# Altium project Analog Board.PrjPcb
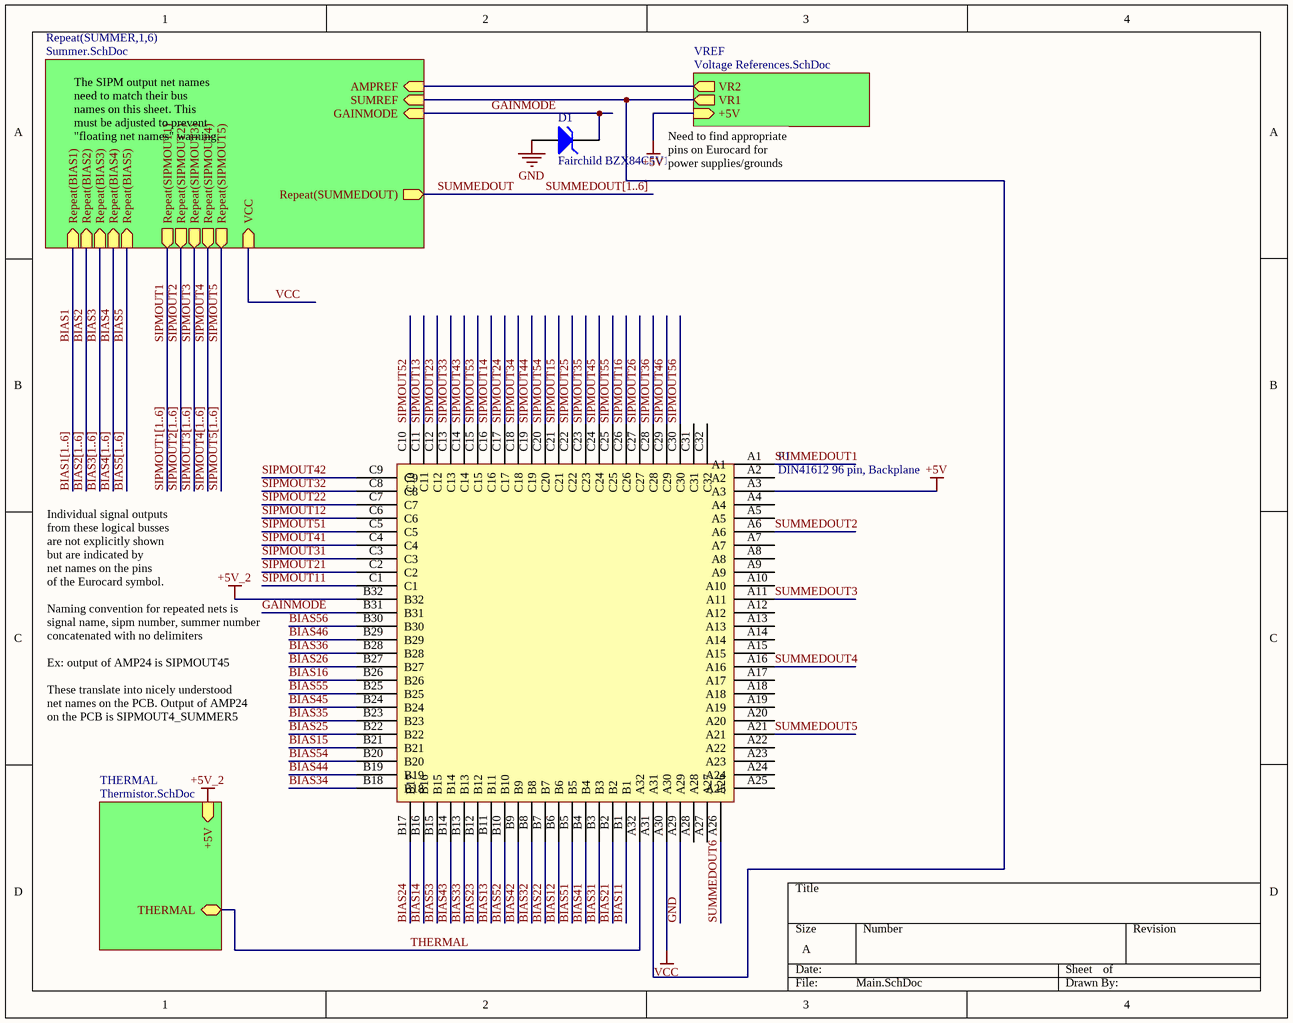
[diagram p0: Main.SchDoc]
5 sheets, 884 parts. Net scope: hierarchical (ports join the sheet entries above them; power ports are global).
Board files: Test PCB.PcbDoc, Amplifier Board.PcbDoc
Sheets:
  Main.SchDoc
    SUMMER1 = Summer.SchDoc
      AMP1 = Amplifier.SchDoc
      AMP2 = Amplifier.SchDoc
      AMP3 = Amplifier.SchDoc
      AMP4 = Amplifier.SchDoc
      AMP5 = Amplifier.SchDoc
    SUMMER2 = Summer.SchDoc
      AMP1 = Amplifier.SchDoc
      AMP2 = Amplifier.SchDoc
      AMP3 = Amplifier.SchDoc
      AMP4 = Amplifier.SchDoc
      AMP5 = Amplifier.SchDoc
    SUMMER3 = Summer.SchDoc
      AMP1 = Amplifier.SchDoc
      AMP2 = Amplifier.SchDoc
      AMP3 = Amplifier.SchDoc
      AMP4 = Amplifier.SchDoc
      AMP5 = Amplifier.SchDoc
    SUMMER4 = Summer.SchDoc
      AMP1 = Amplifier.SchDoc
      AMP2 = Amplifier.SchDoc
      AMP3 = Amplifier.SchDoc
      AMP4 = Amplifier.SchDoc
      AMP5 = Amplifier.SchDoc
    SUMMER5 = Summer.SchDoc
      AMP1 = Amplifier.SchDoc
      AMP2 = Amplifier.SchDoc
      AMP3 = Amplifier.SchDoc
      AMP4 = Amplifier.SchDoc
      AMP5 = Amplifier.SchDoc
    SUMMER6 = Summer.SchDoc
      AMP1 = Amplifier.SchDoc
      AMP2 = Amplifier.SchDoc
      AMP3 = Amplifier.SchDoc
      AMP4 = Amplifier.SchDoc
      AMP5 = Amplifier.SchDoc
    VREF = Voltage References.SchDoc
    THERMAL = Thermistor.SchDoc

## Sheet Main.SchDoc
size A

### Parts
D1  Fairchild BZX84C5V1  [SOT23]
P1  DIN41612 96 pin, Backplane  [EURO2.54-2H96]

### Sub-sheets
Repeat(SUMMER,1,6) = Summer.SchDoc: Repeat(BIAS1) (in), Repeat(SUMMEDOUT) (out), Repeat(SIPMOUT2) (out), Repeat(SIPMOUT5) (out), Repeat(SIPMOUT1) (out), Repeat(SIPMOUT3) (out), Repeat(SIPMOUT4) (out), Repeat(BIAS2) (in), Repeat(BIAS3) (in), Repeat(BIAS4) (in), Repeat(BIAS5) (in), AMPREF (in), SUMREF (in), GAINMODE (in), VCC (in)
THERMAL = Thermistor.SchDoc: THERMAL, +5V (in)
VREF = Voltage References.SchDoc: VR2 (out), VR1 (out), +5V (in)

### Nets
+5V: P1.A3 ; sheet VREF/+5V
+5V_2: P1.B32 ; sheet THERMAL/+5V
GND: D1.1(A) P1.A29
VCC: P1.A30 ; sheet Repeat(SUMMER,1,6)/VCC
BASE1: P1.A31 ; sheet Repeat(SUMMER,1,6)/SUMREF, sheet VREF/VR1
BASE2: sheet Repeat(SUMMER,1,6)/AMPREF, sheet VREF/VR2
BIAS11: P1.B1  [project net BIAS1]
BIAS12: P1.B6  [project net BIAS1]
BIAS13: P1.B11  [project net BIAS1]
BIAS14: P1.B16  [project net BIAS1]
BIAS15: P1.B21  [project net BIAS1]
BIAS16: P1.B26  [project net BIAS1]
BIAS21: P1.B2  [project net BIAS2]
BIAS22: P1.B7  [project net BIAS2]
BIAS23: P1.B12  [project net BIAS2]
BIAS24: P1.B17  [project net BIAS2]
BIAS25: P1.B22  [project net BIAS2]
BIAS26: P1.B27  [project net BIAS2]
BIAS31: P1.B3  [project net BIAS3]
BIAS32: P1.B8  [project net BIAS3]
BIAS33: P1.B13  [project net BIAS3]
BIAS34: P1.B18  [project net BIAS3]
BIAS35: P1.B23  [project net BIAS3]
BIAS36: P1.B28  [project net BIAS3]
BIAS41: P1.B4  [project net BIAS4]
BIAS42: P1.B9  [project net BIAS4]
BIAS43: P1.B14  [project net BIAS4]
BIAS44: P1.B19  [project net BIAS4]
BIAS45: P1.B24  [project net BIAS4]
BIAS46: P1.B29  [project net BIAS4]
BIAS51: P1.B5  [project net BIAS5]
BIAS52: P1.B10  [project net BIAS5]
BIAS53: P1.B15  [project net BIAS5]
BIAS54: P1.B20  [project net BIAS5]
BIAS55: P1.B25  [project net BIAS5]
BIAS56: P1.B30  [project net BIAS5]
GAINMODE: D1.2(K) P1.B31 ; sheet Repeat(SUMMER,1,6)/GAINMODE
SIPMOUT11: P1.C1  [project net SIPMOUT1]
SIPMOUT12: P1.C6  [project net SIPMOUT1]
SIPMOUT13: P1.C11  [project net SIPMOUT1]
SIPMOUT14: P1.C16  [project net SIPMOUT1]
SIPMOUT15: P1.C21  [project net SIPMOUT1]
SIPMOUT16: P1.C26  [project net SIPMOUT1]
SIPMOUT21: P1.C2  [project net SIPMOUT2]
SIPMOUT22: P1.C7  [project net SIPMOUT2]
SIPMOUT23: P1.C12  [project net SIPMOUT2]
SIPMOUT24: P1.C17  [project net SIPMOUT2]
SIPMOUT25: P1.C22  [project net SIPMOUT2]
SIPMOUT26: P1.C27  [project net SIPMOUT2]
SIPMOUT31: P1.C3  [project net SIPMOUT3]
SIPMOUT32: P1.C8  [project net SIPMOUT3]
SIPMOUT33: P1.C13  [project net SIPMOUT3]
SIPMOUT34: P1.C18  [project net SIPMOUT3]
SIPMOUT35: P1.C23  [project net SIPMOUT3]
SIPMOUT36: P1.C28  [project net SIPMOUT3]
SIPMOUT41: P1.C4  [project net SIPMOUT4]
SIPMOUT42: P1.C9  [project net SIPMOUT4]
SIPMOUT43: P1.C14  [project net SIPMOUT4]
SIPMOUT44: P1.C19  [project net SIPMOUT4]
SIPMOUT45: P1.C24  [project net SIPMOUT4]
SIPMOUT46: P1.C29  [project net SIPMOUT4]
SIPMOUT51: P1.C5  [project net SIPMOUT5]
SIPMOUT52: P1.C10  [project net SIPMOUT5]
SIPMOUT53: P1.C15  [project net SIPMOUT5]
SIPMOUT54: P1.C20  [project net SIPMOUT5]
SIPMOUT55: P1.C25  [project net SIPMOUT5]
SIPMOUT56: P1.C30  [project net SIPMOUT5]
SUMMEDOUT1: P1.A1  [project net SUMMEDOUT]
SUMMEDOUT2: P1.A6  [project net SUMMEDOUT]
SUMMEDOUT3: P1.A11  [project net SUMMEDOUT]
SUMMEDOUT4: P1.A16  [project net SUMMEDOUT]
SUMMEDOUT5: P1.A21  [project net SUMMEDOUT]
SUMMEDOUT6: P1.A26  [project net SUMMEDOUT]
THERMAL: P1.A32 ; sheet THERMAL/THERMAL

Not connected (* = marked no-connect by the designer): P1 A2 A4 A5 A7 A8 A9 A10 A12 A13 A14 A15 A17 A18 A19 A20 A22 A23 A24 A25 A27 A28 C31 C32

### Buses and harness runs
bus BIAS1[1..6]
bus BIAS2[1..6]
bus BIAS3[1..6]
bus BIAS4[1..6]
bus BIAS5[1..6]
bus SIPMOUT1[1..6]
bus SIPMOUT2[1..6]
bus SIPMOUT3[1..6]
bus SIPMOUT4[1..6]
bus SIPMOUT5[1..6]
bus SUMMEDOUT[1..6]

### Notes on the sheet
- The SIPM output net names need to match their bus names on this sheet. This must be adjusted to prevent "floating net names" warning.
- Need to find appropriate pins on Eurocard for power supplies/grounds
- Individual signal outputs
  from these logical busses
  are not explicitly shown
  but are indicated by
  net names on the pins
  of the Eurocard symbol.
  Naming convention for repeated nets is
  signal name, sipm number, summer number
  concatenated with no delimiters
  Ex: output of AMP24 is SIPMOUT45
  These translate into nicely understood
  net names on the PCB. Output of AMP24
  on the PCB is SIPMOUT4_SUMMER5

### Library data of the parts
D1 = D Zener: Zener Diode

## Sheet Summer.SchDoc
size A
Used 6 times, as channels SUMMER1, SUMMER2, SUMMER3, SUMMER4, SUMMER5, SUMMER6. Parts and nets are listed once, with the designators drawn on the sheet.
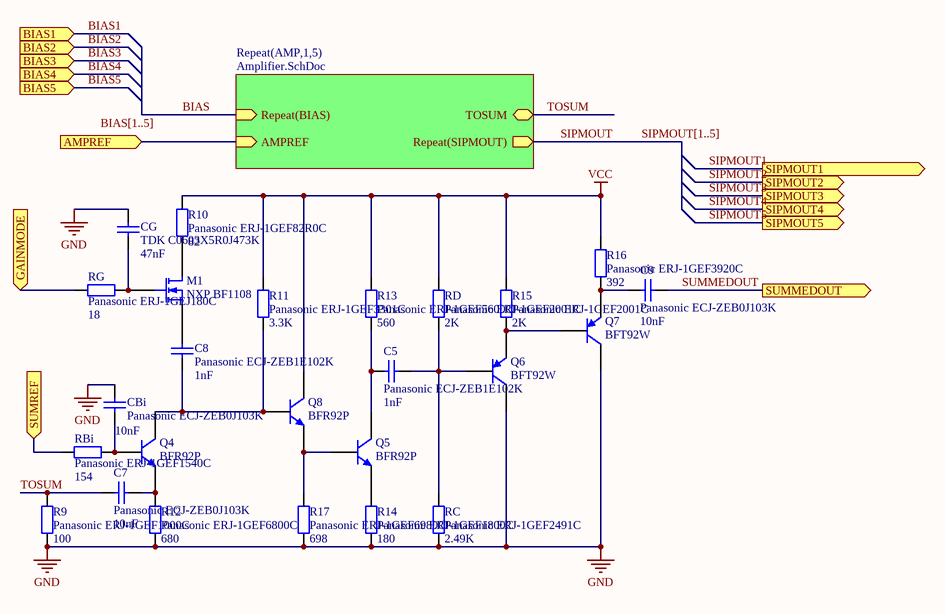
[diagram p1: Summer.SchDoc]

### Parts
C5  Panasonic ECJ-ZEB1E102K  value 1nF  [RESC0603L]
C7  Panasonic ECJ-ZEB0J103K  value 10nF  [RESC0603L]
C8  Panasonic ECJ-ZEB1E102K  value 1nF  [RESC0603L]
C9  Panasonic ECJ-ZEB0J103K  value 10nF  [RESC0603L]
CBi  Panasonic ECJ-ZEB0J103K  value 10nF  [RESC0603L]
CG  TDK C0603X5R0J473K  value 47nF  [RESC0603L]
M1  NXP BF1108  [SOT-143]
Q4  BFR92P  [SOT23_N]
Q5  BFR92P  [SOT23_N]
Q6  BFT92W  [SOT323_L]
Q7  BFT92W  [SOT323_L]
Q8  BFR92P  [SOT23_N]
R9  Panasonic ERJ-1GEF1000C  value 100  [RESC0603L]
R10  Panasonic ERJ-1GEF82R0C  value 82  [RESC0603L]
R11  Panasonic ERJ-1GEF3301C  value 3.3K  [RESC0603L]
R12  Panasonic ERJ-1GEF6800C  value 680  [RESC0603L]
R13  Panasonic ERJ-1GEF5600C  value 560  [RESC0603L]
R14  Panasonic ERJ-1GEF1800C  value 180  [RESC0603L]
R15  Panasonic ERJ-1GEF2001C  value 2K  [RESC0603L]
R16  Panasonic ERJ-1GEF3920C  value 392  [RESC0603L]
R17  Panasonic ERJ-1GEF6980C  value 698  [RESC0603L]
RBi  Panasonic ERJ-1GEF1540C  value 154  [RESC0603L]
RC  Panasonic ERJ-1GEF2491C  value 2.49K  [RESC0603L]
RD  Panasonic ERJ-1GEF2001C  value 2K  [RESC0603L]
RG  Panasonic ERJ-1GEJ180C  value 18  [RESC0603L]

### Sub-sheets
Repeat(AMP,1,5) = Amplifier.SchDoc: Repeat(BIAS) (in), TOSUM (bidir), Repeat(SIPMOUT) (out), AMPREF (in)

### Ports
AMPREF (in), BIAS1 (in), BIAS2 (in), BIAS3 (in), BIAS4 (in), BIAS5 (in), GAINMODE (in), SIPMOUT1 (out), SIPMOUT2 (out), SIPMOUT3 (out), SIPMOUT4 (out), SIPMOUT5 (out), SUMMEDOUT (out), SUMREF (in)

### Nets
GND: CBi.2 CG.2 Q6.3(C) Q7.3(C) R9.1 R12.1 R14.1 R17.1 RC.1
VCC: Q8.3(C) R10.2 R11.2 R13.2 R15.2 R16.2 RD.2
AMPREF: port AMPREF, sheet Repeat(AMP,1,5)/AMPREF
GAINMODE: RG.2 ; port GAINMODE
SUMMEDOUT: C9.2 ; port SUMMEDOUT
SUMREF: RBi.1 ; port SUMREF
TOSUM: C7.1 R9.2 ; sheet Repeat(AMP,1,5)/TOSUM
NetC5_1: C5.1 Q5.3(C) R13.1
NetC5_2: C5.2 Q6.1(B) RC.2 RD.1
NetC7_2: C7.2 Q4.2(E) R12.2
NetC8_1: C8.1 Q4.3(C) Q8.1(B) R11.1
NetC8_2: C8.2 M1.3(S)
NetC9_1: C9.1 Q7.2(E) R16.1
NetCBi_1: CBi.1 Q4.1(B) RBi.2
NetCG_1: CG.1 M1.1(G) RG.1
NetM1_4: M1.4(D) R10.1
NetQ5_1: Q5.1(B) Q8.2(E) R17.2
NetQ5_2: Q5.2(E) R14.2
NetQ6_2: Q6.2(E) Q7.1(B) R15.1

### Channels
SUMMER1: designators end in _SUMMER1; ports AMPREF=BASE2 BIAS1=BIAS1 BIAS2=BIAS2 BIAS3=BIAS3 BIAS4=BIAS4 BIAS5=BIAS5 GAINMODE=GAINMODE SIPMOUT1=SIPMOUT1 SIPMOUT2=SIPMOUT2 SIPMOUT3=SIPMOUT3 SIPMOUT4=SIPMOUT4 SIPMOUT5=SIPMOUT5 SUMMEDOUT=SUMMEDOUT SUMREF=BASE1
SUMMER2: designators end in _SUMMER2; ports AMPREF=BASE2 BIAS1=BIAS1 BIAS2=BIAS2 BIAS3=BIAS3 BIAS4=BIAS4 BIAS5=BIAS5 GAINMODE=GAINMODE SIPMOUT1=SIPMOUT1 SIPMOUT2=SIPMOUT2 SIPMOUT3=SIPMOUT3 SIPMOUT4=SIPMOUT4 SIPMOUT5=SIPMOUT5 SUMMEDOUT=SUMMEDOUT SUMREF=BASE1
SUMMER3: designators end in _SUMMER3; ports AMPREF=BASE2 BIAS1=BIAS1 BIAS2=BIAS2 BIAS3=BIAS3 BIAS4=BIAS4 BIAS5=BIAS5 GAINMODE=GAINMODE SIPMOUT1=SIPMOUT1 SIPMOUT2=SIPMOUT2 SIPMOUT3=SIPMOUT3 SIPMOUT4=SIPMOUT4 SIPMOUT5=SIPMOUT5 SUMMEDOUT=SUMMEDOUT SUMREF=BASE1
SUMMER4: designators end in _SUMMER4; ports AMPREF=BASE2 BIAS1=BIAS1 BIAS2=BIAS2 BIAS3=BIAS3 BIAS4=BIAS4 BIAS5=BIAS5 GAINMODE=GAINMODE SIPMOUT1=SIPMOUT1 SIPMOUT2=SIPMOUT2 SIPMOUT3=SIPMOUT3 SIPMOUT4=SIPMOUT4 SIPMOUT5=SIPMOUT5 SUMMEDOUT=SUMMEDOUT SUMREF=BASE1
SUMMER5: designators end in _SUMMER5; ports AMPREF=BASE2 BIAS1=BIAS1 BIAS2=BIAS2 BIAS3=BIAS3 BIAS4=BIAS4 BIAS5=BIAS5 GAINMODE=GAINMODE SIPMOUT1=SIPMOUT1 SIPMOUT2=SIPMOUT2 SIPMOUT3=SIPMOUT3 SIPMOUT4=SIPMOUT4 SIPMOUT5=SIPMOUT5 SUMMEDOUT=SUMMEDOUT SUMREF=BASE1
SUMMER6: designators end in _SUMMER6; ports AMPREF=BASE2 BIAS1=BIAS1 BIAS2=BIAS2 BIAS3=BIAS3 BIAS4=BIAS4 BIAS5=BIAS5 GAINMODE=GAINMODE SIPMOUT1=SIPMOUT1 SIPMOUT2=SIPMOUT2 SIPMOUT3=SIPMOUT3 SIPMOUT4=SIPMOUT4 SIPMOUT5=SIPMOUT5 SUMMEDOUT=SUMMEDOUT SUMREF=BASE1

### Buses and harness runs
bus BIAS[1..5]
bus SIPMOUT[1..5]

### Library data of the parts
C5 C7-C9 CBi CG = Cap: Capacitor
M1 = MOSFET-N: N-Channel MOSFET; PackageDocument: 1995/1996
Q4 Q5 Q8 = BFR92A: NPN 5 GHz Wideband Transistor
Q6 Q7 = BFT92W: PNP 4 GHz Wideband Transistor
R9-R17 RBi RC RD RG = Res2: Resistor

## Sheet Amplifier.SchDoc
size A
Used 30 times, as channels SUMMER1/AMP1, SUMMER1/AMP2, SUMMER1/AMP3, SUMMER1/AMP4, SUMMER1/AMP5, SUMMER2/AMP1, SUMMER2/AMP2, SUMMER2/AMP3, SUMMER2/AMP4, SUMMER2/AMP5, SUMMER3/AMP1, SUMMER3/AMP2, SUMMER3/AMP3, SUMMER3/AMP4, SUMMER3/AMP5, SUMMER4/AMP1, SUMMER4/AMP2, SUMMER4/AMP3, SUMMER4/AMP4, SUMMER4/AMP5, SUMMER5/AMP1, SUMMER5/AMP2, SUMMER5/AMP3, SUMMER5/AMP4, SUMMER5/AMP5, SUMMER6/AMP1, SUMMER6/AMP2, SUMMER6/AMP3, SUMMER6/AMP4, SUMMER6/AMP5. Parts and nets are listed once, with the designators drawn on the sheet.
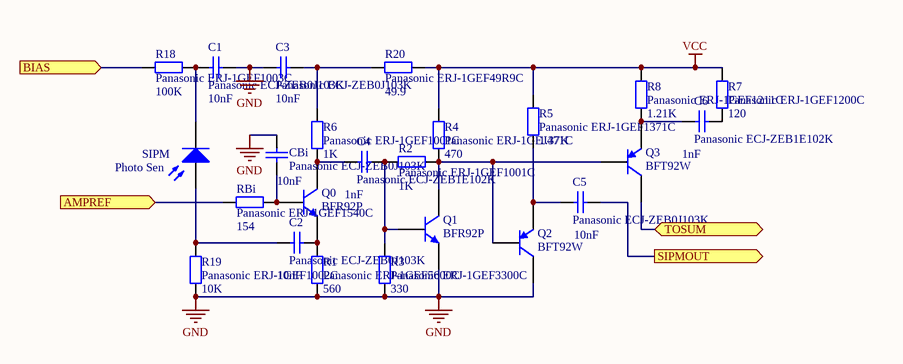
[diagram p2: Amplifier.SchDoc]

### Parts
C1  Panasonic ECJ-ZEB0J103K  value 10nF  [RESC0603L]
C2  Panasonic ECJ-ZEB0J103K  value 10nF  [RESC0603L]
C3  Panasonic ECJ-ZEB0J103K  value 10nF  [RESC0603L]
C4  Panasonic ECJ-ZEB1E102K  value 1nF  [RESC0603L]
C5  Panasonic ECJ-ZEB0J103K  value 10nF  [RESC0603L]
C6  Panasonic ECJ-ZEB1E102K  value 1nF  [RESC0603L]
CBi  Panasonic ECJ-ZEB0J103K  value 10nF  [RESC0603L]
Q0  BFR92P  [SOT23_N]
Q1  BFR92P  [SOT23_N]
Q2  BFT92W  [SOT323_L]
Q3  BFT92W  [SOT323_L]
R1  Panasonic ERJ-1GEF5600C  value 560  [RESC0603L]
R2  Panasonic ERJ-1GEF1001C  value 1K  [RESC0603L]
R3  Panasonic ERJ-1GEF3300C  value 330  [RESC0603L]
R4  Panasonic ERJ-1GEJ471C  value 470  [RESC0603L]
R5  Panasonic ERJ-1GEF1371C  value 1.37K  [RESC0603L]
R6  Panasonic ERJ-1GEF1001C  value 1K  [RESC0603L]
R7  Panasonic ERJ-1GEF1200C  value 120  [RESC0603L]
R8  Panasonic ERJ-1GEF1211C  value 1.21K  [RESC0603L]
R18  Panasonic ERJ-1GEF1003C  value 100K  [RESC0603L]
R19  Panasonic ERJ-1GEF1002C  value 10K  [RESC0603L]
R20  Panasonic ERJ-1GEF49R9C  value 49.9  [RESC0603L]
RBi  Panasonic ERJ-1GEF1540C  value 154  [RESC0603L]
SIPM  Photo Sen  [Photonique SiPM]

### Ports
AMPREF (in), BIAS (in), SIPMOUT (out), TOSUM (bidir)

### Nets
GND: C1.2 C3.1 CBi.2 Q1.2(E) Q2.3(C) R1.1 R3.1 R19.1
VCC: R4.2 R5.2 R7.2 R8.2 R20.2
AMPREF: RBi.1 ; port AMPREF
BIAS: R18.1 ; port BIAS
SIPMOUT: C5.2 ; port SIPMOUT
TOSUM: Q3.3(C) ; port TOSUM
NetC1_1: C1.1 R18.2 SIPM.2(K)
NetC2_1: C2.1 R19.2 SIPM.1(A)
NetC2_2: C2.2 Q0.2(E) R1.2
NetC3_2: C3.2 R6.2 R20.1
NetC4_1: C4.1 Q0.3(C) R6.1
NetC4_2: C4.2 Q1.1(B) R2.1 R3.2
NetC5_1: C5.1 Q2.2(E) R5.1
NetC6_1: C6.1 Q3.2(E) R8.1
NetC6_2: C6.2 R7.1
NetCBi_1: CBi.1 Q0.1(B) RBi.2
NetQ1_3: Q1.3(C) Q2.1(B) Q3.1(B) R2.2 R4.1

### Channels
SUMMER1/AMP1: designators end in _AMP1; ports AMPREF=BASE2 BIAS=BIAS1 SIPMOUT=SIPMOUT1 TOSUM=TOSUM_SUMMER1
SUMMER1/AMP2: designators end in _AMP2; ports AMPREF=BASE2 BIAS=BIAS2 SIPMOUT=SIPMOUT2 TOSUM=TOSUM_SUMMER1
SUMMER1/AMP3: designators end in _AMP3; ports AMPREF=BASE2 BIAS=BIAS3 SIPMOUT=SIPMOUT3 TOSUM=TOSUM_SUMMER1
SUMMER1/AMP4: designators end in _AMP4; ports AMPREF=BASE2 BIAS=BIAS4 SIPMOUT=SIPMOUT4 TOSUM=TOSUM_SUMMER1
SUMMER1/AMP5: designators end in _AMP5; ports AMPREF=BASE2 BIAS=BIAS5 SIPMOUT=SIPMOUT5 TOSUM=TOSUM_SUMMER1
SUMMER2/AMP1: designators end in _AMP6; ports AMPREF=BASE2 BIAS=BIAS1 SIPMOUT=SIPMOUT1 TOSUM=TOSUM_SUMMER2
SUMMER2/AMP2: designators end in _AMP7; ports AMPREF=BASE2 BIAS=BIAS2 SIPMOUT=SIPMOUT2 TOSUM=TOSUM_SUMMER2
SUMMER2/AMP3: designators end in _AMP8; ports AMPREF=BASE2 BIAS=BIAS3 SIPMOUT=SIPMOUT3 TOSUM=TOSUM_SUMMER2
SUMMER2/AMP4: designators end in _AMP9; ports AMPREF=BASE2 BIAS=BIAS4 SIPMOUT=SIPMOUT4 TOSUM=TOSUM_SUMMER2
SUMMER2/AMP5: designators end in _AMP10; ports AMPREF=BASE2 BIAS=BIAS5 SIPMOUT=SIPMOUT5 TOSUM=TOSUM_SUMMER2
SUMMER3/AMP1: designators end in _AMP11; ports AMPREF=BASE2 BIAS=BIAS1 SIPMOUT=SIPMOUT1 TOSUM=TOSUM_SUMMER3
SUMMER3/AMP2: designators end in _AMP12; ports AMPREF=BASE2 BIAS=BIAS2 SIPMOUT=SIPMOUT2 TOSUM=TOSUM_SUMMER3
SUMMER3/AMP3: designators end in _AMP13; ports AMPREF=BASE2 BIAS=BIAS3 SIPMOUT=SIPMOUT3 TOSUM=TOSUM_SUMMER3
SUMMER3/AMP4: designators end in _AMP14; ports AMPREF=BASE2 BIAS=BIAS4 SIPMOUT=SIPMOUT4 TOSUM=TOSUM_SUMMER3
SUMMER3/AMP5: designators end in _AMP15; ports AMPREF=BASE2 BIAS=BIAS5 SIPMOUT=SIPMOUT5 TOSUM=TOSUM_SUMMER3
SUMMER4/AMP1: designators end in _AMP16; ports AMPREF=BASE2 BIAS=BIAS1 SIPMOUT=SIPMOUT1 TOSUM=TOSUM_SUMMER4
SUMMER4/AMP2: designators end in _AMP17; ports AMPREF=BASE2 BIAS=BIAS2 SIPMOUT=SIPMOUT2 TOSUM=TOSUM_SUMMER4
SUMMER4/AMP3: designators end in _AMP18; ports AMPREF=BASE2 BIAS=BIAS3 SIPMOUT=SIPMOUT3 TOSUM=TOSUM_SUMMER4
SUMMER4/AMP4: designators end in _AMP19; ports AMPREF=BASE2 BIAS=BIAS4 SIPMOUT=SIPMOUT4 TOSUM=TOSUM_SUMMER4
SUMMER4/AMP5: designators end in _AMP20; ports AMPREF=BASE2 BIAS=BIAS5 SIPMOUT=SIPMOUT5 TOSUM=TOSUM_SUMMER4
SUMMER5/AMP1: designators end in _AMP21; ports AMPREF=BASE2 BIAS=BIAS1 SIPMOUT=SIPMOUT1 TOSUM=TOSUM_SUMMER5
SUMMER5/AMP2: designators end in _AMP22; ports AMPREF=BASE2 BIAS=BIAS2 SIPMOUT=SIPMOUT2 TOSUM=TOSUM_SUMMER5
SUMMER5/AMP3: designators end in _AMP23; ports AMPREF=BASE2 BIAS=BIAS3 SIPMOUT=SIPMOUT3 TOSUM=TOSUM_SUMMER5
SUMMER5/AMP4: designators end in _AMP24; ports AMPREF=BASE2 BIAS=BIAS4 SIPMOUT=SIPMOUT4 TOSUM=TOSUM_SUMMER5
SUMMER5/AMP5: designators end in _AMP25; ports AMPREF=BASE2 BIAS=BIAS5 SIPMOUT=SIPMOUT5 TOSUM=TOSUM_SUMMER5
SUMMER6/AMP1: designators end in _AMP26; ports AMPREF=BASE2 BIAS=BIAS1 SIPMOUT=SIPMOUT1 TOSUM=TOSUM_SUMMER6
SUMMER6/AMP2: designators end in _AMP27; ports AMPREF=BASE2 BIAS=BIAS2 SIPMOUT=SIPMOUT2 TOSUM=TOSUM_SUMMER6
SUMMER6/AMP3: designators end in _AMP28; ports AMPREF=BASE2 BIAS=BIAS3 SIPMOUT=SIPMOUT3 TOSUM=TOSUM_SUMMER6
SUMMER6/AMP4: designators end in _AMP29; ports AMPREF=BASE2 BIAS=BIAS4 SIPMOUT=SIPMOUT4 TOSUM=TOSUM_SUMMER6
SUMMER6/AMP5: designators end in _AMP30; ports AMPREF=BASE2 BIAS=BIAS5 SIPMOUT=SIPMOUT5 TOSUM=TOSUM_SUMMER6

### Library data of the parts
C1-C6 CBi = Cap: Capacitor
Q0 Q1 = BFR92A: NPN 5 GHz Wideband Transistor
Q2 Q3 = BFT92W: PNP 4 GHz Wideband Transistor
R1-R8 R18-R20 RBi = Res2: Resistor
SIPM = Photo Sen: Photosensitive Diode

## Sheet Voltage References.SchDoc
size A
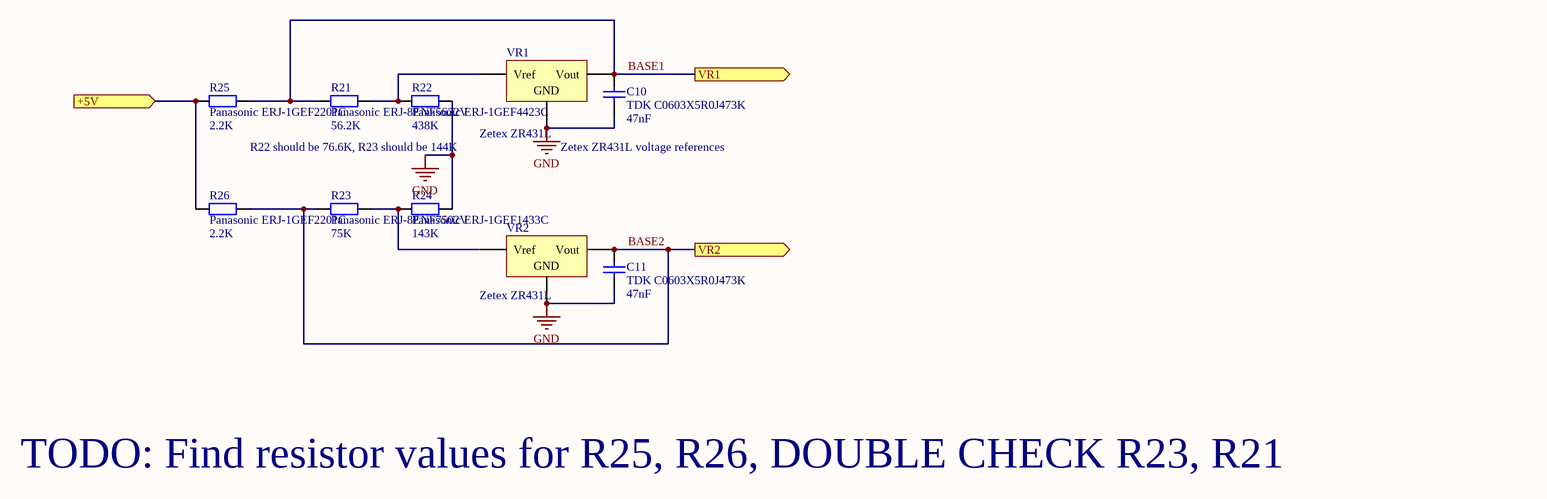
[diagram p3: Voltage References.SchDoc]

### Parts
C10  TDK C0603X5R0J473K  value 47nF  [RESC0603L]
C11  TDK C0603X5R0J473K  value 47nF  [RESC0603L]
R21  Panasonic ERJ-8ENF5622V  value 56.2K  [RESC3216L]
R22  Panasonic ERJ-1GEF4423C  value 438K  [RESC0603L]
R23  Panasonic ERJ-8ENF7502V  value 75K  [RESC3216L]
R24  Panasonic ERJ-1GEF1433C  value 143K  [RESC0603L]
R25  Panasonic ERJ-1GEF2201C  value 2.2K  [RESC0603L]
R26  Panasonic ERJ-1GEF2201C  value 2.2K  [RESC0603L]
VR1  Zetex ZR431L  [SOT23_L]
VR2  Zetex ZR431L  [SOT23_L]

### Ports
+5V (in), VR1 (out), VR2 (out)

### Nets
+5V: R25.1 R26.1 ; port +5V
GND: C10.1 C11.1 R22.2 R24.2 VR1.2(GND) VR2.2(GND)
BASE1: C10.2 R21.1 R25.2 VR1.3(Vout) ; port VR1
BASE2: C11.2 R23.1 R26.2 VR2.3(Vout) ; port VR2
NetR21_2: R21.2 R22.1 VR1.1(Vref)
NetR23_2: R23.2 R24.1 VR2.1(Vref)

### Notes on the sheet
- R22 should be 76.6K, R23 should be 144K
- Zetex ZR431L voltage references
- TODO: Find resistor values for R25, R26, DOUBLE CHECK R23, R21

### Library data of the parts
C10 C11 = Cap: Capacitor
R21-R26 = Res2: Resistor
VR1 VR2 = Volt Reg: Voltage Regulator

## Sheet Thermistor.SchDoc
size A
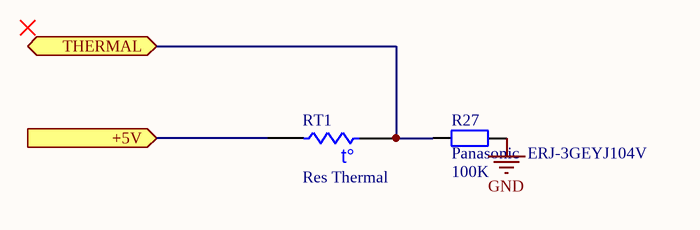
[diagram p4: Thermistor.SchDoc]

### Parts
R27  Panasonic  ERJ-3GEYJ104V  value 100K  [RESC1608L]
RT1  Res Thermal  [RESC1608L]

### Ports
+5V (in), THERMAL

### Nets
+5V_2: RT1.2 ; port +5V
GND: R27.2
THERMAL: R27.1 RT1.1 ; port THERMAL

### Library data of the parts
R27 = Res2: Resistor
RT1 = Res Thermal: Thermistor

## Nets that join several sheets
+5V: Main (P1.A3), Voltage References (R25.1 R26.1)
+5V_2: Main (P1.B32), Thermistor (RT1.2)
GND: Main (D1.1 P1.A29), SUMMER1 (9 pins), SUMMER1/AMP1 (8 pins), SUMMER1/AMP2 (8 pins), SUMMER1/AMP3 (8 pins), SUMMER1/AMP4 (8 pins), SUMMER1/AMP5 (8 pins), SUMMER2 (9 pins), SUMMER2/AMP1 (8 pins), SUMMER2/AMP2 (8 pins), SUMMER2/AMP3 (8 pins), SUMMER2/AMP4 (8 pins), SUMMER2/AMP5 (8 pins), SUMMER3 (9 pins), SUMMER3/AMP1 (8 pins), SUMMER3/AMP2 (8 pins), SUMMER3/AMP3 (8 pins), SUMMER3/AMP4 (8 pins), SUMMER3/AMP5 (8 pins), SUMMER4 (9 pins), SUMMER4/AMP1 (8 pins), SUMMER4/AMP2 (8 pins), SUMMER4/AMP3 (8 pins), SUMMER4/AMP4 (8 pins), SUMMER4/AMP5 (8 pins), SUMMER5 (9 pins), SUMMER5/AMP1 (8 pins), SUMMER5/AMP2 (8 pins), SUMMER5/AMP3 (8 pins), SUMMER5/AMP4 (8 pins), SUMMER5/AMP5 (8 pins), SUMMER6 (9 pins), SUMMER6/AMP1 (8 pins), SUMMER6/AMP2 (8 pins), SUMMER6/AMP3 (8 pins), SUMMER6/AMP4 (8 pins), SUMMER6/AMP5 (8 pins), Voltage References (6 pins), Thermistor (R27.2)
VCC: Main (P1.A30), SUMMER1 (7 pins), SUMMER1/AMP1 (5 pins), SUMMER1/AMP2 (5 pins), SUMMER1/AMP3 (5 pins), SUMMER1/AMP4 (5 pins), SUMMER1/AMP5 (5 pins), SUMMER2 (7 pins), SUMMER2/AMP1 (5 pins), SUMMER2/AMP2 (5 pins), SUMMER2/AMP3 (5 pins), SUMMER2/AMP4 (5 pins), SUMMER2/AMP5 (5 pins), SUMMER3 (7 pins), SUMMER3/AMP1 (5 pins), SUMMER3/AMP2 (5 pins), SUMMER3/AMP3 (5 pins), SUMMER3/AMP4 (5 pins), SUMMER3/AMP5 (5 pins), SUMMER4 (7 pins), SUMMER4/AMP1 (5 pins), SUMMER4/AMP2 (5 pins), SUMMER4/AMP3 (5 pins), SUMMER4/AMP4 (5 pins), SUMMER4/AMP5 (5 pins), SUMMER5 (7 pins), SUMMER5/AMP1 (5 pins), SUMMER5/AMP2 (5 pins), SUMMER5/AMP3 (5 pins), SUMMER5/AMP4 (5 pins), SUMMER5/AMP5 (5 pins), SUMMER6 (7 pins), SUMMER6/AMP1 (5 pins), SUMMER6/AMP2 (5 pins), SUMMER6/AMP3 (5 pins), SUMMER6/AMP4 (5 pins), SUMMER6/AMP5 (5 pins)
BASE1: Main (P1.A31), SUMMER1 (RBi_SUMMER1.1), SUMMER2 (RBi_SUMMER2.1), SUMMER3 (RBi_SUMMER3.1), SUMMER4 (RBi_SUMMER4.1), SUMMER5 (RBi_SUMMER5.1), SUMMER6 (RBi_SUMMER6.1), Voltage References (C10.2 R21.1 R25.2 VR1.3)
BASE2: SUMMER1/AMP1 (RBi_AMP1.1), SUMMER1/AMP2 (RBi_AMP2.1), SUMMER1/AMP3 (RBi_AMP3.1), SUMMER1/AMP4 (RBi_AMP4.1), SUMMER1/AMP5 (RBi_AMP5.1), SUMMER2/AMP1 (RBi_AMP6.1), SUMMER2/AMP2 (RBi_AMP7.1), SUMMER2/AMP3 (RBi_AMP8.1), SUMMER2/AMP4 (RBi_AMP9.1), SUMMER2/AMP5 (RBi_AMP10.1), SUMMER3/AMP1 (RBi_AMP11.1), SUMMER3/AMP2 (RBi_AMP12.1), SUMMER3/AMP3 (RBi_AMP13.1), SUMMER3/AMP4 (RBi_AMP14.1), SUMMER3/AMP5 (RBi_AMP15.1), SUMMER4/AMP1 (RBi_AMP16.1), SUMMER4/AMP2 (RBi_AMP17.1), SUMMER4/AMP3 (RBi_AMP18.1), SUMMER4/AMP4 (RBi_AMP19.1), SUMMER4/AMP5 (RBi_AMP20.1), SUMMER5/AMP1 (RBi_AMP21.1), SUMMER5/AMP2 (RBi_AMP22.1), SUMMER5/AMP3 (RBi_AMP23.1), SUMMER5/AMP4 (RBi_AMP24.1), SUMMER5/AMP5 (RBi_AMP25.1), SUMMER6/AMP1 (RBi_AMP26.1), SUMMER6/AMP2 (RBi_AMP27.1), SUMMER6/AMP3 (RBi_AMP28.1), SUMMER6/AMP4 (RBi_AMP29.1), SUMMER6/AMP5 (RBi_AMP30.1), Voltage References (C11.2 R23.1 R26.2 VR2.3)
BIAS1: Main (P1.B1), SUMMER1/AMP1 (R18_AMP1.1)
BIAS1: Main (P1.B6), SUMMER2/AMP1 (R18_AMP6.1)
BIAS1: Main (P1.B11), SUMMER3/AMP1 (R18_AMP11.1)
BIAS1: Main (P1.B16), SUMMER4/AMP1 (R18_AMP16.1)
BIAS1: Main (P1.B21), SUMMER5/AMP1 (R18_AMP21.1)
BIAS1: Main (P1.B26), SUMMER6/AMP1 (R18_AMP26.1)
BIAS2: Main (P1.B2), SUMMER1/AMP2 (R18_AMP2.1)
BIAS2: Main (P1.B7), SUMMER2/AMP2 (R18_AMP7.1)
BIAS2: Main (P1.B12), SUMMER3/AMP2 (R18_AMP12.1)
BIAS2: Main (P1.B17), SUMMER4/AMP2 (R18_AMP17.1)
BIAS2: Main (P1.B22), SUMMER5/AMP2 (R18_AMP22.1)
BIAS2: Main (P1.B27), SUMMER6/AMP2 (R18_AMP27.1)
BIAS3: Main (P1.B3), SUMMER1/AMP3 (R18_AMP3.1)
BIAS3: Main (P1.B8), SUMMER2/AMP3 (R18_AMP8.1)
BIAS3: Main (P1.B13), SUMMER3/AMP3 (R18_AMP13.1)
BIAS3: Main (P1.B18), SUMMER4/AMP3 (R18_AMP18.1)
BIAS3: Main (P1.B23), SUMMER5/AMP3 (R18_AMP23.1)
BIAS3: Main (P1.B28), SUMMER6/AMP3 (R18_AMP28.1)
BIAS4: Main (P1.B4), SUMMER1/AMP4 (R18_AMP4.1)
BIAS4: Main (P1.B9), SUMMER2/AMP4 (R18_AMP9.1)
BIAS4: Main (P1.B14), SUMMER3/AMP4 (R18_AMP14.1)
BIAS4: Main (P1.B19), SUMMER4/AMP4 (R18_AMP19.1)
BIAS4: Main (P1.B24), SUMMER5/AMP4 (R18_AMP24.1)
BIAS4: Main (P1.B29), SUMMER6/AMP4 (R18_AMP29.1)
BIAS5: Main (P1.B5), SUMMER1/AMP5 (R18_AMP5.1)
BIAS5: Main (P1.B10), SUMMER2/AMP5 (R18_AMP10.1)
BIAS5: Main (P1.B15), SUMMER3/AMP5 (R18_AMP15.1)
BIAS5: Main (P1.B20), SUMMER4/AMP5 (R18_AMP20.1)
BIAS5: Main (P1.B25), SUMMER5/AMP5 (R18_AMP25.1)
BIAS5: Main (P1.B30), SUMMER6/AMP5 (R18_AMP30.1)
GAINMODE: Main (D1.2 P1.B31), SUMMER1 (RG_SUMMER1.2), SUMMER2 (RG_SUMMER2.2), SUMMER3 (RG_SUMMER3.2), SUMMER4 (RG_SUMMER4.2), SUMMER5 (RG_SUMMER5.2), SUMMER6 (RG_SUMMER6.2)
SIPMOUT1: Main (P1.C1), SUMMER1/AMP1 (C5_AMP1.2)
SIPMOUT1: Main (P1.C6), SUMMER2/AMP1 (C5_AMP6.2)
SIPMOUT1: Main (P1.C11), SUMMER3/AMP1 (C5_AMP11.2)
SIPMOUT1: Main (P1.C16), SUMMER4/AMP1 (C5_AMP16.2)
SIPMOUT1: Main (P1.C21), SUMMER5/AMP1 (C5_AMP21.2)
SIPMOUT1: Main (P1.C26), SUMMER6/AMP1 (C5_AMP26.2)
SIPMOUT2: Main (P1.C2), SUMMER1/AMP2 (C5_AMP2.2)
SIPMOUT2: Main (P1.C7), SUMMER2/AMP2 (C5_AMP7.2)
SIPMOUT2: Main (P1.C12), SUMMER3/AMP2 (C5_AMP12.2)
SIPMOUT2: Main (P1.C17), SUMMER4/AMP2 (C5_AMP17.2)
SIPMOUT2: Main (P1.C22), SUMMER5/AMP2 (C5_AMP22.2)
SIPMOUT2: Main (P1.C27), SUMMER6/AMP2 (C5_AMP27.2)
SIPMOUT3: Main (P1.C3), SUMMER1/AMP3 (C5_AMP3.2)
SIPMOUT3: Main (P1.C8), SUMMER2/AMP3 (C5_AMP8.2)
SIPMOUT3: Main (P1.C13), SUMMER3/AMP3 (C5_AMP13.2)
SIPMOUT3: Main (P1.C18), SUMMER4/AMP3 (C5_AMP18.2)
SIPMOUT3: Main (P1.C23), SUMMER5/AMP3 (C5_AMP23.2)
SIPMOUT3: Main (P1.C28), SUMMER6/AMP3 (C5_AMP28.2)
SIPMOUT4: Main (P1.C4), SUMMER1/AMP4 (C5_AMP4.2)
SIPMOUT4: Main (P1.C9), SUMMER2/AMP4 (C5_AMP9.2)
SIPMOUT4: Main (P1.C14), SUMMER3/AMP4 (C5_AMP14.2)
SIPMOUT4: Main (P1.C19), SUMMER4/AMP4 (C5_AMP19.2)
SIPMOUT4: Main (P1.C24), SUMMER5/AMP4 (C5_AMP24.2)
SIPMOUT4: Main (P1.C29), SUMMER6/AMP4 (C5_AMP29.2)
SIPMOUT5: Main (P1.C5), SUMMER1/AMP5 (C5_AMP5.2)
SIPMOUT5: Main (P1.C10), SUMMER2/AMP5 (C5_AMP10.2)
SIPMOUT5: Main (P1.C15), SUMMER3/AMP5 (C5_AMP15.2)
SIPMOUT5: Main (P1.C20), SUMMER4/AMP5 (C5_AMP20.2)
SIPMOUT5: Main (P1.C25), SUMMER5/AMP5 (C5_AMP25.2)
SIPMOUT5: Main (P1.C30), SUMMER6/AMP5 (C5_AMP30.2)
SUMMEDOUT: Main (P1.A1), SUMMER1 (C9_SUMMER1.2)
SUMMEDOUT: Main (P1.A6), SUMMER2 (C9_SUMMER2.2)
SUMMEDOUT: Main (P1.A11), SUMMER3 (C9_SUMMER3.2)
SUMMEDOUT: Main (P1.A16), SUMMER4 (C9_SUMMER4.2)
SUMMEDOUT: Main (P1.A21), SUMMER5 (C9_SUMMER5.2)
SUMMEDOUT: Main (P1.A26), SUMMER6 (C9_SUMMER6.2)
THERMAL: Main (P1.A32), Thermistor (R27.1 RT1.1)
TOSUM_SUMMER1: SUMMER1 (C7_SUMMER1.1 R9_SUMMER1.2), SUMMER1/AMP1 (Q3_AMP1.3), SUMMER1/AMP2 (Q3_AMP2.3), SUMMER1/AMP3 (Q3_AMP3.3), SUMMER1/AMP4 (Q3_AMP4.3), SUMMER1/AMP5 (Q3_AMP5.3)
TOSUM_SUMMER2: SUMMER2 (C7_SUMMER2.1 R9_SUMMER2.2), SUMMER2/AMP1 (Q3_AMP6.3), SUMMER2/AMP2 (Q3_AMP7.3), SUMMER2/AMP3 (Q3_AMP8.3), SUMMER2/AMP4 (Q3_AMP9.3), SUMMER2/AMP5 (Q3_AMP10.3)
TOSUM_SUMMER3: SUMMER3 (C7_SUMMER3.1 R9_SUMMER3.2), SUMMER3/AMP1 (Q3_AMP11.3), SUMMER3/AMP2 (Q3_AMP12.3), SUMMER3/AMP3 (Q3_AMP13.3), SUMMER3/AMP4 (Q3_AMP14.3), SUMMER3/AMP5 (Q3_AMP15.3)
TOSUM_SUMMER4: SUMMER4 (C7_SUMMER4.1 R9_SUMMER4.2), SUMMER4/AMP1 (Q3_AMP16.3), SUMMER4/AMP2 (Q3_AMP17.3), SUMMER4/AMP3 (Q3_AMP18.3), SUMMER4/AMP4 (Q3_AMP19.3), SUMMER4/AMP5 (Q3_AMP20.3)
TOSUM_SUMMER5: SUMMER5 (C7_SUMMER5.1 R9_SUMMER5.2), SUMMER5/AMP1 (Q3_AMP21.3), SUMMER5/AMP2 (Q3_AMP22.3), SUMMER5/AMP3 (Q3_AMP23.3), SUMMER5/AMP4 (Q3_AMP24.3), SUMMER5/AMP5 (Q3_AMP25.3)
TOSUM_SUMMER6: SUMMER6 (C7_SUMMER6.1 R9_SUMMER6.2), SUMMER6/AMP1 (Q3_AMP26.3), SUMMER6/AMP2 (Q3_AMP27.3), SUMMER6/AMP3 (Q3_AMP28.3), SUMMER6/AMP4 (Q3_AMP29.3), SUMMER6/AMP5 (Q3_AMP30.3)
